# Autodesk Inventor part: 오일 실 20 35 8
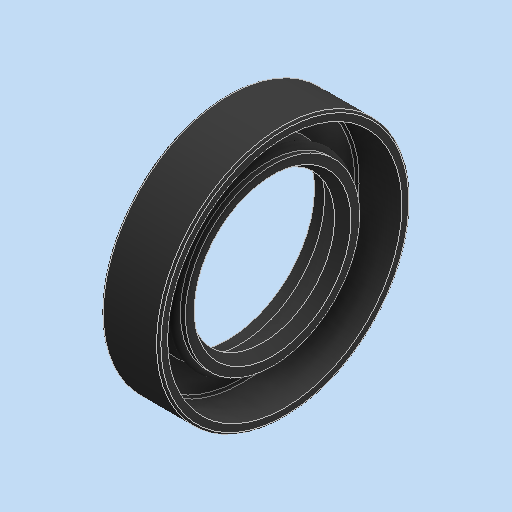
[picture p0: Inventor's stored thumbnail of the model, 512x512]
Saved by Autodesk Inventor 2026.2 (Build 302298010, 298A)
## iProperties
Created: 2026-03
Part Number: 오일 실 20 35 8
Material: 고무
Description: 오일-실
Document SubType Name: Modeling
Designer: PC-2-06
Density: 0.93 g/cm^3
Appearance: 기본값
Author: jhkim
Sending System: Autodesk Inventor 2026
Preprocessor: ST-DEVELOPER v20.1
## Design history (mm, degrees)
feature "Solid1"
node "솔리드1"
